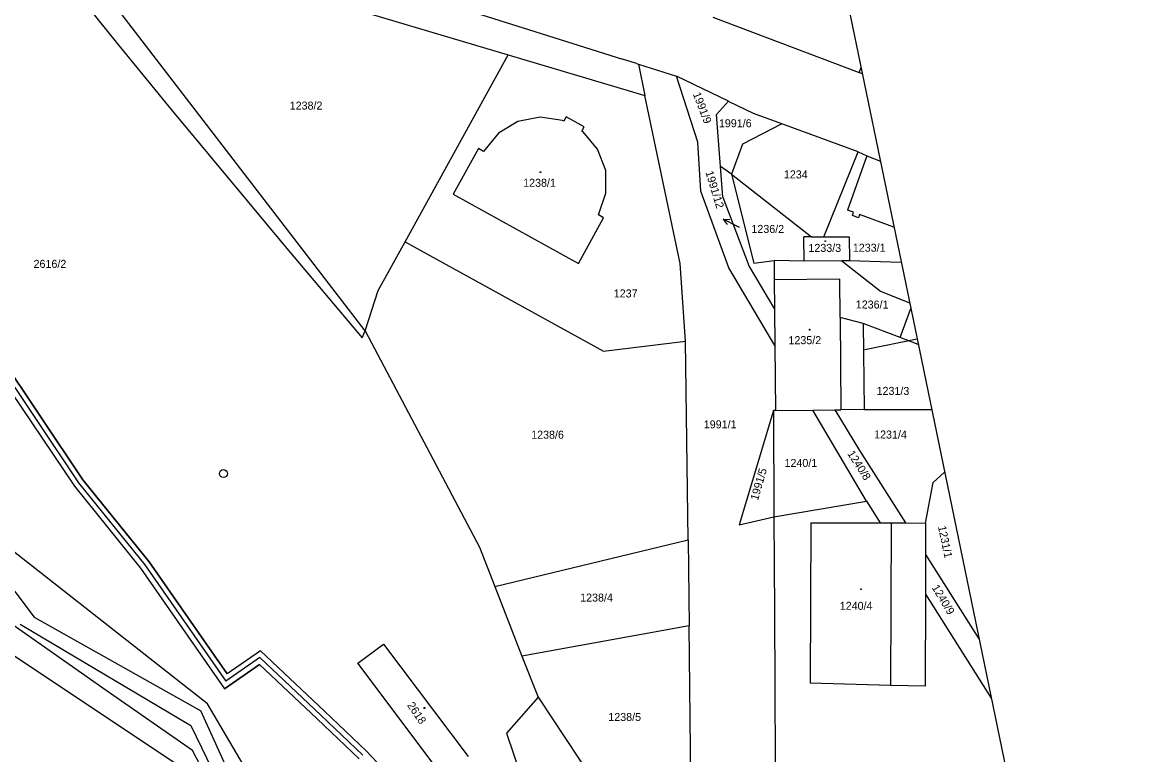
# Model space of a CAD drawing. Extents: x -804166 to -803706, y -1151030 to -1150147.
# Drawn here: x -804000.6 to -803790.5, y -1150430.9 to -1150293.8 of the extents above; entities that cross this region are included whole.
import ezdxf

# ---------------------------------------------------------------- set-up
doc = ezdxf.new("R2010")
doc.units = 0
for name, color, linetype in [('Default', 7, 'Continuous'), ('formát', 7, 'Continuous'), ('kilometráž - vrstava 7', 7, 'Continuous'), ('kn_celek - Cisla parcel pomocna', 7, 'Continuous'), ('kn_celek - Cisla pozemkovych parcel', 7, 'Continuous'), ('kn_celek - Cisla stavebnich parcel', 7, 'Continuous'), ('kn_celek - Hranice parcel', 7, 'Continuous'), ('kn_celek - Vnitrni kresby', 7, 'Continuous'), ('kn_celek - Znacky budov', 7, 'Continuous'), ('plochy - CD', 7, 'Continuous'), ('plochy - VB', 7, 'Continuous'), ('PSR_C2_2_trasa_Vimperk - Kabelová trasa', 7, 'Continuous')]:
    doc.layers.add(name, color=color, linetype=linetype)

# ---------------------------------------------------------------- blocks, each defined once
blk = doc.blocks.new('402')
at = {"layer": 'Default'}
for p, q in [((-0.8, 0.8), (0.7, 0.8)), ((-0.8, 0.8), (-0.8, -0.7)), ((0.7, 0.8), (0.7, -0.7)), ((0.7, -0.7), (-0.8, -0.7))]:
    blk.add_line(p, q, dxfattribs=at)
blk = doc.blocks.new('Z61')
at = {"layer": 'Default'}
for p, q in [((0, 0), (30, 0)), ((30, 0), (19.2, 5.3)), ((30, 0), (19.2, -5.3))]:
    blk.add_line(p, q, dxfattribs=at)

msp = doc.modelspace()

# ---------------------------------------------------------------- linework, layer by layer
at = {"layer": 'formát'}
for p, q in [((-803875.43, -1150147.35), (-803832.97, -1150353.01)), ((-803842.77, -1150355.03), (-803832.97, -1150353.01)), ((-803842.77, -1150355.03), (-803832.97, -1150353.01)), ((-803832.97, -1150353.01), (-803790.51, -1150558.67))]:
    msp.add_line(p, q, dxfattribs=at)
at = {"layer": 'kilometráž - vrstava 7'}
msp.add_circle((-803962.96, -1150378.29), 0.75, dxfattribs=at)
at = {"layer": 'kn_celek - Cisla parcel pomocna'}
msp.add_line((-803866.21, -1150332.19), (-803866.6, -1150332), dxfattribs=at)
at = {"layer": 'kn_celek - Hranice parcel'}
for p, q in [((-803997.02, -1150280.06), (-803982.8, -1150297.76)), ((-803956.46, -1150279.09), (-803906.79, -1150294.77)), ((-803964.13, -1150283.6), (-803909.59, -1150299.84)), ((-803936.41, -1150351.52), (-803985.68, -1150287.47)), ((-803871.21, -1150292.78), (-803843.78, -1150303.13)), ((-803906.79, -1150294.77), (-803888.15, -1150300.65)), ((-803982.8, -1150297.76), (-803972.77, -1150310.06)), ((-803928.92, -1150334.86), (-803909.59, -1150299.84)), ((-803909.59, -1150299.84), (-803883.95, -1150307.46)), ((-803885.56, -1150301.47), (-803888.15, -1150300.65)), ((-803885.56, -1150301.47), (-803885.18, -1150301.59)), ((-803885.18, -1150301.59), (-803883.95, -1150307.46)), ((-803885.18, -1150301.59), (-803878.06, -1150303.84)), ((-803868.32, -1150308.54), (-803878.06, -1150303.84)), ((-803874.05, -1150316.22), (-803878.06, -1150303.84)), ((-803843.78, -1150303.13), (-803843.45, -1150302.24)), ((-803843.78, -1150303.13), (-803843.23, -1150303.33)), ((-803877.38, -1150338.95), (-803883.95, -1150307.46)), ((-803972.77, -1150310.06), (-803951.37, -1150335.75)), ((-803870.53, -1150311.05), (-803868.32, -1150308.54)), ((-803868.15, -1150308.62), (-803868.32, -1150308.54)), ((-803863.62, -1150310.81), (-803868.15, -1150308.62)), ((-803907.78, -1150312.34), (-803911.43, -1150314.53)), ((-803903.59, -1150311.53), (-803907.78, -1150312.34)), ((-803899.41, -1150312.13), (-803903.59, -1150311.53)), ((-803899.17, -1150312.27), (-803899.41, -1150312.13)), ((-803898.7, -1150311.45), (-803899.17, -1150312.27)), ((-803895.36, -1150313.32), (-803898.7, -1150311.45)), ((-803869.79, -1150320.77), (-803870.53, -1150311.05)), ((-803858.32, -1150312.76), (-803863.62, -1150310.81)), ((-803911.43, -1150314.53), (-803914.21, -1150317.92)), ((-803895.79, -1150314.16), (-803895.36, -1150313.32)), ((-803895.56, -1150314.26), (-803895.79, -1150314.16)), ((-803892.83, -1150317.5), (-803895.56, -1150314.26)), ((-803858.32, -1150312.76), (-803865.69, -1150316.56)), ((-803844.01, -1150318.03), (-803858.32, -1150312.76)), ((-803873.46, -1150325.4), (-803874.05, -1150316.22)), ((-803865.69, -1150316.56), (-803867.71, -1150322.2)), ((-803915.17, -1150317.39), (-803919.91, -1150325.93)), ((-803914.21, -1150317.92), (-803915.17, -1150317.39)), ((-803891.3, -1150321.48), (-803892.83, -1150317.5)), ((-803850.46, -1150333.95), (-803844.01, -1150318.03)), ((-803844.01, -1150318.03), (-803842.37, -1150318.79)), ((-803842.37, -1150318.79), (-803839.84, -1150319.73)), ((-803867.71, -1150322.2), (-803869.79, -1150320.77)), ((-803869.35, -1150326.49), (-803869.79, -1150320.77)), ((-803891.26, -1150325.75), (-803891.3, -1150321.48)), ((-803867.71, -1150322.2), (-803852.76, -1150333.95)), ((-803867.71, -1150322.2), (-803863.58, -1150338.88)), ((-803919.91, -1150325.93), (-803896.43, -1150338.92)), ((-803892.65, -1150329.83), (-803891.26, -1150325.75)), ((-803868.24, -1150339.72), (-803873.46, -1150325.4)), ((-803869.35, -1150326.49), (-803864.44, -1150339.47)), ((-803896.43, -1150338.92), (-803891.7, -1150330.37)), ((-803891.7, -1150330.37), (-803892.65, -1150329.83)), ((-803933.96, -1150343.99), (-803928.92, -1150334.86)), ((-803928.92, -1150334.86), (-803926.07, -1150336.43)), ((-803852.76, -1150333.95), (-803854.16, -1150333.95)), ((-803854.09, -1150338.49), (-803854.16, -1150333.95)), ((-803852.76, -1150333.95), (-803850.46, -1150333.95)), ((-803850.46, -1150333.95), (-803845.68, -1150333.94)), ((-803845.68, -1150333.94), (-803845.65, -1150338.42)), ((-803951.37, -1150335.75), (-803936.98, -1150352.88)), ((-803926.07, -1150336.43), (-803891.7, -1150355.35)), ((-803876.34, -1150353.49), (-803877.38, -1150338.95)), ((-803859.59, -1150354.3), (-803868.24, -1150339.72)), ((-803864.44, -1150339.47), (-803859.66, -1150347.47)), ((-803863.58, -1150338.88), (-803859.74, -1150338.36)), ((-803854.09, -1150338.49), (-803859.74, -1150338.36)), ((-803859.74, -1150338.36), (-803859.71, -1150341.99)), ((-803847.07, -1150338.43), (-803854.09, -1150338.49)), ((-803845.65, -1150338.42), (-803847.07, -1150338.43)), ((-803847.07, -1150338.43), (-803839.84, -1150344.11)), ((-803835.92, -1150338.74), (-803845.65, -1150338.42)), ((-803847.42, -1150341.88), (-803859.71, -1150341.99)), ((-803847.37, -1150349.05), (-803847.42, -1150341.88)), ((-803936.41, -1150351.52), (-803933.96, -1150343.99)), ((-803859.71, -1150341.99), (-803859.66, -1150347.47)), ((-803839.84, -1150344.11), (-803834.36, -1150346.29)), ((-803859.66, -1150347.47), (-803859.59, -1150354.3)), ((-803836.11, -1150352.82), (-803834.14, -1150347.36)), ((-803843.07, -1150350.14), (-803847.37, -1150349.05)), ((-803836.11, -1150352.82), (-803843.07, -1150350.14)), ((-803843.07, -1150350.14), (-803842.9, -1150366.29)), ((-803936.98, -1150352.88), (-803936.41, -1150351.52)), ((-803936.41, -1150351.52), (-803914.94, -1150392.05)), ((-803891.7, -1150355.35), (-803876.34, -1150353.49)), ((-803875.87, -1150390.71), (-803876.34, -1150353.49)), ((-803859.59, -1150354.3), (-803859.48, -1150366.48)), ((-803832.74, -1150354.12), (-803836.11, -1150352.82)), ((-803859.89, -1150366.48), (-803866.31, -1150387.9)), ((-803859.89, -1150366.48), (-803859.79, -1150386.4)), ((-803859.48, -1150366.48), (-803859.89, -1150366.48)), ((-803859.48, -1150366.48), (-803852.47, -1150366.4)), ((-803852.47, -1150366.4), (-803848.37, -1150366.36)), ((-803842.46, -1150383.45), (-803852.47, -1150366.4)), ((-803848.37, -1150366.36), (-803847.27, -1150366.35)), ((-803848.37, -1150366.36), (-803843.75, -1150373.97)), ((-803842.9, -1150366.29), (-803847.27, -1150366.35)), ((-803842.9, -1150366.29), (-803830.23, -1150366.29)), ((-803843.75, -1150373.97), (-803835.14, -1150387.53)), ((-803829.93, -1150379.96), (-803827.81, -1150378.02)), ((-803831.37, -1150387.58), (-803829.93, -1150379.96)), ((-803859.79, -1150386.4), (-803842.46, -1150383.45)), ((-803842.46, -1150383.45), (-803839.89, -1150387.5)), ((-803866.31, -1150387.9), (-803859.79, -1150386.4)), ((-803859.79, -1150386.4), (-803859.7, -1150404.14)), ((-803852.89, -1150387.49), (-803853, -1150417.55)), ((-803852.89, -1150387.49), (-803839.89, -1150387.5)), ((-803839.89, -1150387.5), (-803837.83, -1150387.5)), ((-803837.83, -1150387.5), (-803835.14, -1150387.53)), ((-803835.14, -1150387.53), (-803831.37, -1150387.58)), ((-803831.37, -1150387.58), (-803831.39, -1150393.44)), ((-803965.92, -1150421.41), (-804004.05, -1150391.51)), ((-803914.94, -1150392.05), (-803912.08, -1150399.4)), ((-803912.08, -1150399.4), (-803875.87, -1150390.71)), ((-803875.87, -1150390.71), (-803875.68, -1150406.78)), ((-803831.39, -1150393.44), (-803831.41, -1150400.87)), ((-803831.39, -1150393.44), (-803821.37, -1150409.22)), ((-804026.79, -1150395.95), (-803971.47, -1150432.84)), ((-803912.08, -1150399.4), (-803907, -1150412.45)), ((-803831.41, -1150400.87), (-803831.45, -1150418.12)), ((-803831.41, -1150400.87), (-803819.08, -1150420.32)), ((-803984.95, -1150418.93), (-804006.42, -1150403.82)), ((-803859.7, -1150404.14), (-803859.55, -1150432.31)), ((-803875.68, -1150406.78), (-803907, -1150412.45)), ((-803875.26, -1150441.02), (-803875.68, -1150406.78)), ((-803937.77, -1150413.78), (-803932.96, -1150410.23)), ((-803932.96, -1150410.23), (-803917.09, -1150431.3)), ((-803907, -1150412.45), (-803903.99, -1150420.19)), ((-803921.93, -1150434.85), (-803937.77, -1150413.78)), ((-803837.96, -1150417.98), (-803853, -1150417.55)), ((-803968.72, -1150430.14), (-803984.95, -1150418.93)), ((-803831.45, -1150418.12), (-803837.96, -1150417.98)), ((-803953.58, -1150442.45), (-803965.92, -1150421.41)), ((-803903.99, -1150420.19), (-803909.89, -1150426.9)), ((-803903.99, -1150420.19), (-803887.28, -1150445.33)), ((-803909.89, -1150426.9), (-803907.15, -1150435.03)), ((-803963.14, -1150440.87), (-803968.72, -1150430.14))]:
    msp.add_line(p, q, dxfattribs=at)
at = {"layer": 'kn_celek - Vnitrni kresby'}
for p, q in [((-803842.37, -1150318.79), (-803846.02, -1150328.92)), ((-803844.87, -1150329.34), (-803846.02, -1150328.92)), ((-803845.09, -1150329.95), (-803844.87, -1150329.34)), ((-803843.96, -1150330.36), (-803845.09, -1150329.95)), ((-803843.74, -1150329.75), (-803843.96, -1150330.36)), ((-803837.29, -1150332.11), (-803843.74, -1150329.75)), ((-803847.37, -1150349.05), (-803847.27, -1150366.35)), ((-803837.83, -1150387.5), (-803837.96, -1150417.98)), ((-804006.14, -1150394.97), (-803998.39, -1150405.19)), ((-804001.06, -1150406.5), (-803969.03, -1150425.49)), ((-803998.39, -1150405.19), (-803967.2, -1150422.72)), ((-803958.04, -1150442.71), (-803967.2, -1150422.72)), ((-803969.03, -1150425.49), (-803961.6, -1150440.81))]:
    msp.add_line(p, q, dxfattribs=at)
at = {"layer": 'plochy - CD'}
for p, q in [((-803978.48, -1150396), (-803962.72, -1150418.58)), ((-803962.23, -1150415.8), (-803976.88, -1150394.8)), ((-803956.01, -1150411.47), (-803962.23, -1150415.8)), ((-803943.99, -1150422.78), (-803956.01, -1150411.47)), ((-803962.72, -1150418.58), (-803956.2, -1150414.04)), ((-803956.2, -1150414.04), (-803945.37, -1150424.23)), ((-803936.11, -1150430.3), (-803943.99, -1150422.78)), ((-803945.37, -1150424.23), (-803937.53, -1150431.71)), ((-803926.23, -1150440.67), (-803936.11, -1150430.3))]:
    msp.add_line(p, q, dxfattribs=at)
for points in [[(-803976.88, -1150394.8), (-803989.28, -1150379.42), (-804005.25, -1150355.72)], [(-804006.89, -1150356.88), (-803990.89, -1150380.61), (-803978.48, -1150396)]]:
    msp.add_lwpolyline(points, dxfattribs=at)
at = {"layer": 'plochy - VB'}
for p, q in [((-803978.48, -1150396), (-803962.72, -1150418.58)), ((-803976.88, -1150394.8), (-803962.23, -1150415.8)), ((-803956.01, -1150411.47), (-803962.23, -1150415.8)), ((-803956.01, -1150411.47), (-803943.99, -1150422.78)), ((-803956.2, -1150414.04), (-803962.72, -1150418.58)), ((-803956.2, -1150414.04), (-803945.37, -1150424.23)), ((-803943.99, -1150422.78), (-803936.11, -1150430.3)), ((-803945.37, -1150424.23), (-803937.53, -1150431.71)), ((-803936.11, -1150430.3), (-803926.23, -1150440.67))]:
    msp.add_line(p, q, dxfattribs=at)
for points in [[(-804005.25, -1150355.72), (-803989.28, -1150379.42), (-803976.88, -1150394.8)], [(-804006.89, -1150356.88), (-803990.89, -1150380.61), (-803978.48, -1150396)]]:
    msp.add_lwpolyline(points, dxfattribs=at)
at = {"layer": 'PSR_C2_2_trasa_Vimperk - Kabelová trasa'}
for p, q in [((-803977.68, -1150395.4), (-803962.48, -1150417.19)), ((-803956.11, -1150412.75), (-803962.48, -1150417.19)), ((-803956.11, -1150412.75), (-803944.68, -1150423.51)), ((-803944.68, -1150423.51), (-803936.82, -1150431))]:
    msp.add_line(p, q, dxfattribs=at)
msp.add_lwpolyline([(-804006.07, -1150356.3), (-803990.08, -1150380.01), (-803977.68, -1150395.4)], dxfattribs=at)

# ---------------------------------------------------------------- block references
at = {"layer": 'kn_celek - Cisla parcel pomocna', "xscale": 0.1, "yscale": 0.09999999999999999, "rotation": 153.36036000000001}
msp.add_blockref('Z61', (-803866.6, -1150332), dxfattribs=at)
at = {"layer": 'kn_celek - Znacky budov', "xscale": 0.1, "yscale": 0.10000000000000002}
for p in [(-803903.56, -1150321.81), (-803850.18, -1150334.76), (-803853.11, -1150351.32), (-803843.51, -1150399.92), (-803925.3, -1150422.2)]:
    msp.add_blockref('402', p, dxfattribs=at)

# ---------------------------------------------------------------- texts
at = {"layer": 'kn_celek - Cisla parcel pomocna'}
msp.add_text('1991/12', height=1.5, rotation=287.0851, dxfattribs=at).set_placement((-803872.65, -1150321.82))
at = {"layer": 'kn_celek - Cisla pozemkovych parcel'}
for s, rotation, p in [('1991/9', 291.1449, (-803875.01, -1150307.17)), ('1234', 359.706, (-803857.92, -1150322.98)), ('1236/2', 359.706, (-803864.01, -1150333.19)), ('1236/1', 359.706, (-803844.45, -1150347.35)), ('1231/3', 359.706, (-803840.55, -1150363.53)), ('1231/4', 359.706, (-803841.01, -1150371.7)), ('1240/8', 302.6192, (-803846.09, -1150374.54)), ('1991/5', 73.8, (-803862.79, -1150383.42)), ('1231/1', 281.9456, (-803829.05, -1150388.21)), ('1240/9', 300.9725, (-803830.26, -1150399.63))]:
    msp.add_text(s, height=1.5, rotation=rotation, dxfattribs=at).set_placement(p)
for s, height, p in [('1238/2', 1.5, (-803950.53, -1150310.1)), ('1991/6', 1.5, (-803870.1, -1150313.41)), ('1991/12', 0.1, (-803866.51, -1150332.16)), ('2616/2', 1.5, (-803998.53, -1150339.75)), ('1237', 1.5, (-803889.8, -1150345.29)), ('1991/1', 1.5, (-803872.93, -1150369.81)), ('1238/6', 1.5, (-803905.28, -1150371.75)), ('1240/1', 1.5, (-803857.8, -1150377.04)), ('1238/4', 1.5, (-803896.1, -1150402.26)), ('1238/5', 1.5, (-803890.82, -1150424.62))]:
    msp.add_text(s, height=height, dxfattribs=at).set_placement(p)
at = {"layer": 'kn_celek - Cisla stavebnich parcel'}
for s, p in [('1238/1', (-803906.78, -1150324.56)), ('1233/3', (-803853.32, -1150336.76)), ('1233/1', (-803845, -1150336.72)), ('1240/4', (-803847.45, -1150403.8))]:
    msp.add_text(s, height=1.5, dxfattribs=at).set_placement(p)
for s, rotation, p in [('1235/2', 0.022, (-803857.06, -1150354.04)), ('2618', 304.0459, (-803928.58, -1150421.68))]:
    msp.add_text(s, height=1.5, rotation=rotation, dxfattribs=at).set_placement(p)

doc.saveas('drawing.dxf')
